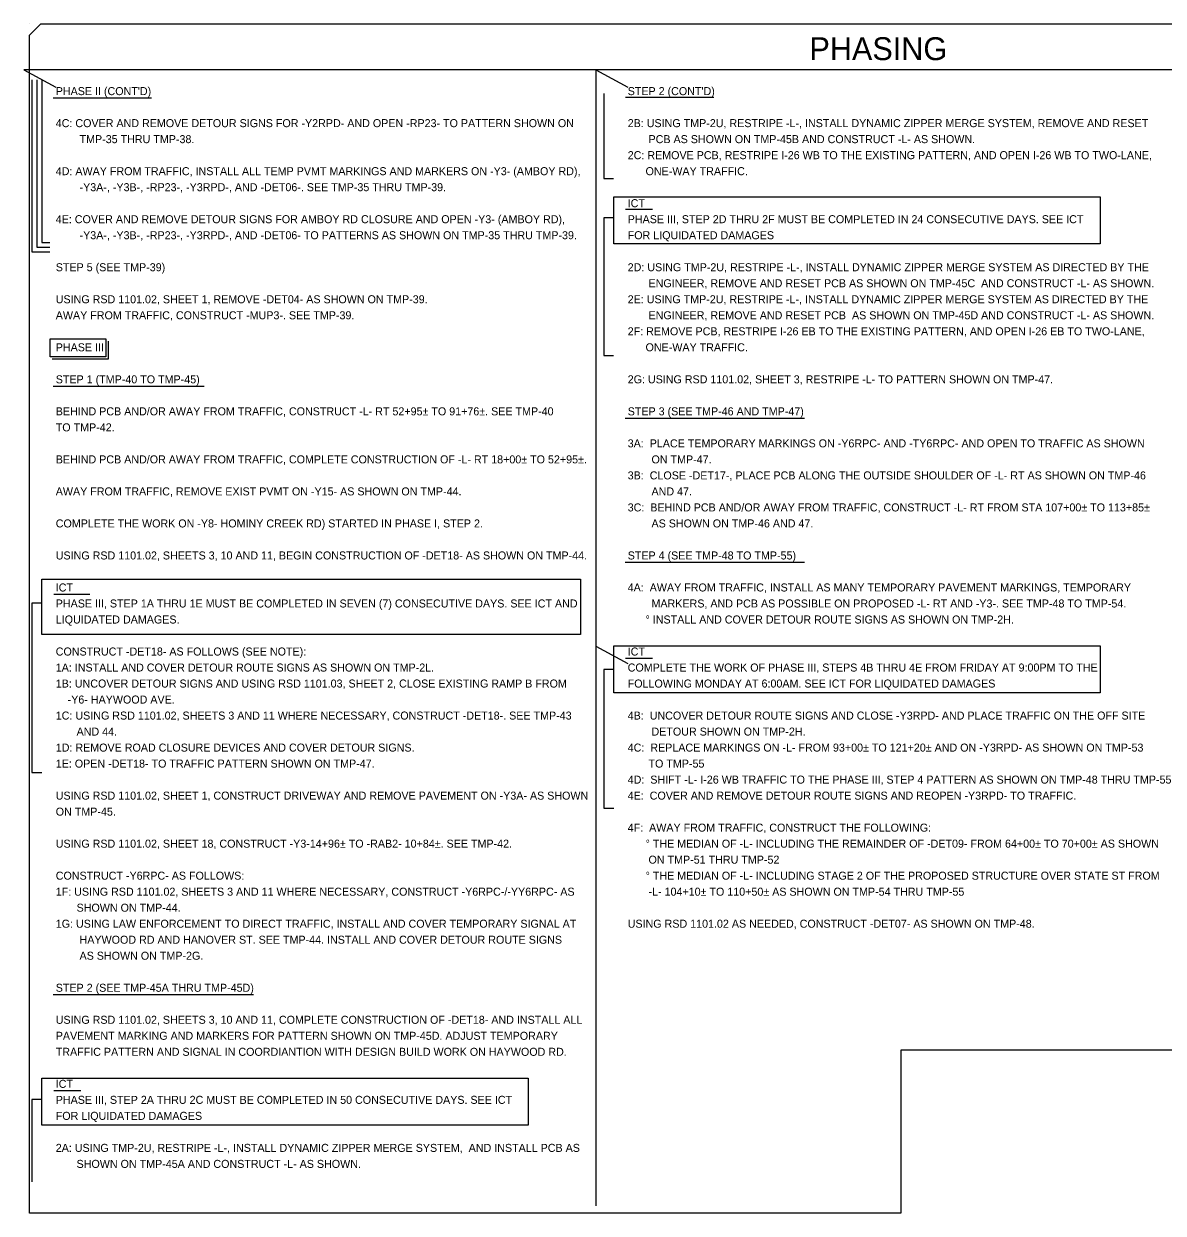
# Model space of a CAD drawing. Extents: x 2483905 to 2494512, y 366160 to 372330.
# Drawn here: x 2491012 to 2492008, y 370218 to 371258 of the extents above; entities that cross this region are included whole.
import ezdxf

# ---------------------------------------------------------------- set-up
doc = ezdxf.new("R2010")
doc.units = 0
for name, color, linetype in [('Scratch_Level_3', 7, 'Continuous'), ('Scratch_Level_6', 7, 'Continuous'), ('TC SHEET BORDER LINE THIN', 7, 'Continuous'), ('TC SHEET LAYOUT SHAPE', 7, 'Continuous'), ('TC SHEET TEXT', 7, 'Continuous')]:
    doc.layers.add(name, color=color, linetype=linetype)

msp = doc.modelspace()

# ---------------------------------------------------------------- linework, layer by layer
at = {"layer": 'Scratch_Level_3'}
msp.add_line((2491016.6, 371258.3), (2491016.6, 371258.3), dxfattribs=at)
at = {"layer": 'Scratch_Level_6'}
for p, q in [((2491011.6, 371218), (2491039.5, 371202.9)), ((2491511.6, 371218), (2491539.5, 371202.9)), ((2491511.6, 370714), (2491539.5, 370698.9))]:
    msp.add_line(p, q, dxfattribs=at)
at = {"layer": 'TC SHEET BORDER LINE THIN'}
for p, q in [((2492511.6, 371218), (2491011.6, 371218)), ((2491511.6, 371218), (2491511.6, 370224.8)), ((2491037.3, 371193.4), (2491123.3, 371193.4)), ((2491537.7, 371194.2), (2491614.9, 371194.2)), ((2491537.7, 371096.2), (2491561.3, 371096.2)), ((2491023, 371063), (2491034.3, 371063)), ((2491027.4, 371067), (2491034.3, 371067)), ((2491018.5, 371059), (2491034.3, 371059)), ((2491037.3, 370941.4), (2491169.2, 370941.4)), ((2491537.3, 370913.4), (2491694.1, 370913.4)), ((2491537.3, 370787.4), (2491694.1, 370787.4)), ((2491037.7, 370759.5), (2491069.2, 370759.5)), ((2491537.7, 370703.5), (2491561.3, 370703.5)), ((2491037.3, 370409.4), (2491212.4, 370409.4)), ((2491037.7, 370325.5), (2491061.3, 370325.5))]:
    msp.add_line(p, q, dxfattribs=at)
for points in [[(2491018.5, 371209.2), (2491018.5, 371059)], [(2491023, 371209.2), (2491023, 371063)], [(2491027.4, 371209.2), (2491027.4, 371067)], [(2491518.6, 371197.3), (2491518.6, 371123), (2491527, 371123)], [(2491527.3, 371088.5), (2491518.6, 371088.5), (2491518.6, 370968.2), (2491527, 370968.2)], [(2491085.4, 370980.7), (2491085.4, 370965), (2491036.5, 370965)], [(2491027.3, 370751.8), (2491018.6, 370751.8), (2491018.6, 370603.6), (2491027.3, 370603.6)], [(2491527.3, 370693.8), (2491518.6, 370693.8), (2491518.6, 370572.5), (2491527.3, 370572.5)], [(2491027.3, 370317.8), (2491018.6, 370317.8), (2491018.6, 370245.7)]]:
    msp.add_lwpolyline(points, dxfattribs=at)
for points in [[(2491527.3, 371107.1), (2491952.5, 371107.1), (2491952.5, 371065.9), (2491527.3, 371065.9)], [(2491034.5, 370982.7), (2491083.4, 370982.7), (2491083.4, 370967), (2491034.5, 370967)], [(2491027.3, 370772.6), (2491498.3, 370772.6), (2491498.3, 370724.3), (2491027.3, 370724.3)], [(2491527.3, 370714.4), (2491952.5, 370714.4), (2491952.5, 370673.2), (2491527.3, 370673.2)], [(2491027.3, 370336.4), (2491452.4, 370336.4), (2491452.4, 370295.2), (2491027.3, 370295.2)]]:
    msp.add_lwpolyline(points, close=True, dxfattribs=at)
at = {"layer": 'TC SHEET LAYOUT SHAPE'}
msp.add_lwpolyline([(2491016.6, 370666.8), (2491016.6, 370976.2), (2491016.6, 371248.3), (2491026.6, 371258.3), (2491469.6, 371258.3), (2491940.6, 371258.3), (2492261.6, 371258.3), (2492261.6, 371178.3), (2492346.6, 371178.3), (2492346.6, 371226.3), (2492506.6, 371226.3), (2492506.6, 370891.3), (2492506.6, 370612.1), (2492506.6, 370360.8), (2491778.4, 370360.8), (2491778.4, 370218.3), (2491608.9, 370218.3), (2491256.1, 370218.3), (2491016.6, 370218.3)], close=True, dxfattribs=at)

# ---------------------------------------------------------------- texts
at = {"layer": 'TC SHEET BORDER LINE THIN'}
for s, p in [("PHASE II (CONT'D)", (2491039.5, 371195.9)), ("STEP 2 (CONT'D)", (2491539.5, 371195.9)), ('4C: COVER AND REMOVE DETOUR SIGNS FOR -Y2RPD- AND OPEN -RP23- TO PATTERN SHOWN ON', (2491039.5, 371167.9)), ('2B: USING TMP-2U, RESTRIPE -L-, INSTALL DYNAMIC ZIPPER MERGE SYSTEM, REMOVE AND RESET ', (2491539.5, 371167.9)), ('        TMP-35 THRU TMP-38.', (2491039.5, 371153.9)), ('       PCB AS SHOWN ON TMP-45B AND CONSTRUCT -L- AS SHOWN.', (2491539.5, 371153.9)), ('2C: REMOVE PCB, RESTRIPE I-26 WB TO THE EXISTING PATTERN, AND OPEN I-26 WB TO TWO-LANE,', (2491539.5, 371139.9)), ('4D: AWAY FROM TRAFFIC, INSTALL ALL TEMP PVMT MARKINGS AND MARKERS ON -Y3- (AMBOY RD),', (2491039.5, 371125.9)), ('      ONE-WAY TRAFFIC.', (2491539.5, 371125.9)), ('        -Y3A-, -Y3B-, -RP23-, -Y3RPD-, AND -DET06-. SEE TMP-35 THRU TMP-39.', (2491039.5, 371111.9)), ('ICT', (2491539.5, 371097.9)), ('4E: COVER AND REMOVE DETOUR SIGNS FOR AMBOY RD CLOSURE AND OPEN -Y3- (AMBOY RD),', (2491039.5, 371083.9)), ('PHASE III, STEP 2D THRU 2F MUST BE COMPLETED IN 24 CONSECUTIVE DAYS. SEE ICT', (2491539.5, 371083.9)), ('        -Y3A-, -Y3B-, -RP23-, -Y3RPD-, AND -DET06- TO PATTERNS AS SHOWN ON TMP-35 THRU TMP-39.', (2491039.5, 371069.9)), ('FOR LIQUIDATED DAMAGES', (2491539.5, 371069.9)), ('STEP 5 (SEE TMP-39)', (2491039.5, 371041.9)), ('2D: USING TMP-2U, RESTRIPE -L-, INSTALL DYNAMIC ZIPPER MERGE SYSTEM AS DIRECTED BY THE ', (2491539.5, 371041.9)), ('       ENGINEER, REMOVE AND RESET PCB AS SHOWN ON TMP-45C  AND CONSTRUCT -L- AS SHOWN.', (2491539.5, 371027.9)), ('USING RSD 1101.02, SHEET 1, REMOVE -DET04- AS SHOWN ON TMP-39.', (2491039.5, 371013.9)), ('2E: USING TMP-2U, RESTRIPE -L-, INSTALL DYNAMIC ZIPPER MERGE SYSTEM AS DIRECTED BY THE ', (2491539.5, 371013.9)), ('AWAY FROM TRAFFIC, CONSTRUCT -MUP3-. SEE TMP-39.', (2491039.5, 370999.9)), ('       ENGINEER, REMOVE AND RESET PCB  AS SHOWN ON TMP-45D AND CONSTRUCT -L- AS SHOWN.', (2491539.5, 370999.9)), ('2F: REMOVE PCB, RESTRIPE I-26 EB TO THE EXISTING PATTERN, AND OPEN I-26 EB TO TWO-LANE,', (2491539.5, 370985.9)), ('PHASE III', (2491039.5, 370971.9)), ('      ONE-WAY TRAFFIC.', (2491539.5, 370971.9)), ('STEP 1 (TMP-40 TO TMP-45)', (2491039.5, 370943.9)), ('2G: USING RSD 1101.02, SHEET 3, RESTRIPE -L- TO PATTERN SHOWN ON TMP-47.', (2491539.5, 370943.9)), ('BEHIND PCB AND/OR AWAY FROM TRAFFIC, CONSTRUCT -L- RT 52+95± TO 91+76±. SEE TMP-40', (2491039.5, 370915.9)), ('STEP 3 (SEE TMP-46 AND TMP-47)', (2491539.5, 370915.9)), ('TO TMP-42.', (2491039.5, 370901.9)), ('3A:  PLACE TEMPORARY MARKINGS ON -Y6RPC- AND -TY6RPC- AND OPEN TO TRAFFIC AS SHOWN', (2491539.5, 370887.9)), ('BEHIND PCB AND/OR AWAY FROM TRAFFIC, COMPLETE CONSTRUCTION OF -L- RT 18+00± TO 52+95±.', (2491039.5, 370873.9)), ('        ON TMP-47.', (2491539.5, 370873.9)), ('3B:  CLOSE -DET17-, PLACE PCB ALONG THE OUTSIDE SHOULDER OF -L- RT AS SHOWN ON TMP-46', (2491539.5, 370859.9)), ('AWAY FROM TRAFFIC, REMOVE EXIST PVMT ON -Y15- AS SHOWN ON TMP-44.', (2491039.5, 370845.9)), ('        AND 47.', (2491539.5, 370845.9)), ('3C:  BEHIND PCB AND/OR AWAY FROM TRAFFIC, CONSTRUCT -L- RT FROM STA 107+00± TO 113+85±', (2491539.5, 370831.9)), ('COMPLETE THE WORK ON -Y8- HOMINY CREEK RD) STARTED IN PHASE I, STEP 2.', (2491039.5, 370817.9)), ('        AS SHOWN ON TMP-46 AND 47.', (2491539.5, 370817.9)), ('USING RSD 1101.02, SHEETS 3, 10 AND 11, BEGIN CONSTRUCTION OF -DET18- AS SHOWN ON TMP-44.', (2491039.5, 370789.9)), ('STEP 4 (SEE TMP-48 TO TMP-55)', (2491539.5, 370789.9)), ('ICT', (2491039.5, 370761.9)), ('4A:  AWAY FROM TRAFFIC, INSTALL AS MANY TEMPORARY PAVEMENT MARKINGS, TEMPORARY', (2491539.5, 370761.9)), ('PHASE III, STEP 1A THRU 1E MUST BE COMPLETED IN SEVEN (7) CONSECUTIVE DAYS. SEE ICT AND ', (2491039.5, 370747.9)), ('        MARKERS, AND PCB AS POSSIBLE ON PROPOSED -L- RT AND -Y3-. SEE TMP-48 TO TMP-54.', (2491539.5, 370747.9)), ('LIQUIDATED DAMAGES.', (2491039.5, 370733.9)), ('      ° INSTALL AND COVER DETOUR ROUTE SIGNS AS SHOWN ON TMP-2H.', (2491539.5, 370733.9)), ('CONSTRUCT -DET18- AS FOLLOWS (SEE NOTE):', (2491039.5, 370705.9)), ('ICT', (2491539.5, 370705.9)), ('1A: INSTALL AND COVER DETOUR ROUTE SIGNS AS SHOWN ON TMP-2L.', (2491039.5, 370691.9)), ('COMPLETE THE WORK OF PHASE III, STEPS 4B THRU 4E FROM FRIDAY AT 9:00PM TO THE', (2491539.5, 370691.9)), ('1B: UNCOVER DETOUR SIGNS AND USING RSD 1101.03, SHEET 2, CLOSE EXISTING RAMP B FROM', (2491039.5, 370677.9)), ('FOLLOWING MONDAY AT 6:00AM. SEE ICT FOR LIQUIDATED DAMAGES', (2491539.5, 370677.9)), ('    -Y6- HAYWOOD AVE.', (2491039.5, 370663.9)), ('1C: USING RSD 1101.02, SHEETS 3 AND 11 WHERE NECESSARY, CONSTRUCT -DET18-. SEE TMP-43 ', (2491039.5, 370649.9)), ('4B:  UNCOVER DETOUR ROUTE SIGNS AND CLOSE -Y3RPD- AND PLACE TRAFFIC ON THE OFF SITE', (2491539.5, 370649.9)), ('       AND 44.', (2491039.5, 370635.9)), ('        DETOUR SHOWN ON TMP-2H.', (2491539.5, 370635.9)), ('1D: REMOVE ROAD CLOSURE DEVICES AND COVER DETOUR SIGNS.', (2491039.5, 370621.9)), ('4C:  REPLACE MARKINGS ON -L- FROM 93+00± TO 121+20± AND ON -Y3RPD- AS SHOWN ON TMP-53', (2491539.5, 370621.9)), ('1E: OPEN -DET18- TO TRAFFIC PATTERN SHOWN ON TMP-47.', (2491039.5, 370607.9)), ('       TO TMP-55', (2491539.5, 370607.9)), ('4D:  SHIFT -L- I-26 WB TRAFFIC TO THE PHASE III, STEP 4 PATTERN AS SHOWN ON TMP-48 THRU TMP-55', (2491539.5, 370593.9)), ('USING RSD 1101.02, SHEET 1, CONSTRUCT DRIVEWAY AND REMOVE PAVEMENT ON -Y3A- AS SHOWN ', (2491039.5, 370579.9)), ('4E:  COVER AND REMOVE DETOUR ROUTE SIGNS AND REOPEN -Y3RPD- TO TRAFFIC.', (2491539.5, 370579.9)), ('ON TMP-45.', (2491039.5, 370565.9)), ('4F:  AWAY FROM TRAFFIC, CONSTRUCT THE FOLLOWING:', (2491539.5, 370551.9)), ('USING RSD 1101.02, SHEET 18, CONSTRUCT -Y3-14+96± TO -RAB2- 10+84±. SEE TMP-42.', (2491039.5, 370537.9)), ('      ° THE MEDIAN OF -L- INCLUDING THE REMAINDER OF -DET09- FROM 64+00± TO 70+00± AS SHOWN', (2491539.5, 370537.9)), ('       ON TMP-51 THRU TMP-52', (2491539.5, 370523.9)), ('CONSTRUCT -Y6RPC- AS FOLLOWS:', (2491039.5, 370509.9)), ('      ° THE MEDIAN OF -L- INCLUDING STAGE 2 OF THE PROPOSED STRUCTURE OVER STATE ST FROM', (2491539.5, 370509.9)), ('1F: USING RSD 1101.02, SHEETS 3 AND 11 WHERE NECESSARY, CONSTRUCT -Y6RPC-/-YY6RPC- AS', (2491039.5, 370495.9)), ('       -L- 104+10± TO 110+50± AS SHOWN ON TMP-54 THRU TMP-55', (2491539.5, 370495.9)), ('       SHOWN ON TMP-44.', (2491039.5, 370481.9)), ('1G: USING LAW ENFORCEMENT TO DIRECT TRAFFIC, INSTALL AND COVER TEMPORARY SIGNAL AT', (2491039.5, 370467.9)), ('USING RSD 1101.02 AS NEEDED, CONSTRUCT -DET07- AS SHOWN ON TMP-48.', (2491539.5, 370467.9)), ('        HAYWOOD RD AND HANOVER ST. SEE TMP-44. INSTALL AND COVER DETOUR ROUTE SIGNS', (2491039.5, 370453.9)), ('        AS SHOWN ON TMP-2G.', (2491039.5, 370439.9)), ('STEP 2 (SEE TMP-45A THRU TMP-45D)', (2491039.5, 370411.9)), ('USING RSD 1101.02, SHEETS 3, 10 AND 11, COMPLETE CONSTRUCTION OF -DET18- AND INSTALL ALL', (2491039.5, 370383.9)), ('PAVEMENT MARKING AND MARKERS FOR PATTERN SHOWN ON TMP-45D. ADJUST TEMPORARY', (2491039.5, 370369.9)), ('TRAFFIC PATTERN AND SIGNAL IN COORDIANTION WITH DESIGN BUILD WORK ON HAYWOOD RD.', (2491039.5, 370355.9)), ('ICT', (2491039.5, 370327.9)), ('PHASE III, STEP 2A THRU 2C MUST BE COMPLETED IN 50 CONSECUTIVE DAYS. SEE ICT', (2491039.5, 370313.9)), ('FOR LIQUIDATED DAMAGES', (2491039.5, 370299.9)), ('2A: USING TMP-2U, RESTRIPE -L-, INSTALL DYNAMIC ZIPPER MERGE SYSTEM,  AND INSTALL PCB AS ', (2491039.5, 370271.9)), ('       SHOWN ON TMP-45A AND CONSTRUCT -L- AS SHOWN.', (2491039.5, 370257.9))]:
    msp.add_text(s, height=7, dxfattribs=at).set_placement(p)
at = {"layer": 'TC SHEET TEXT'}
msp.add_text('PHASING', height=20, rotation=359.9999, dxfattribs=at).set_placement((2491698.4, 371226.5))

doc.saveas('drawing.dxf')
